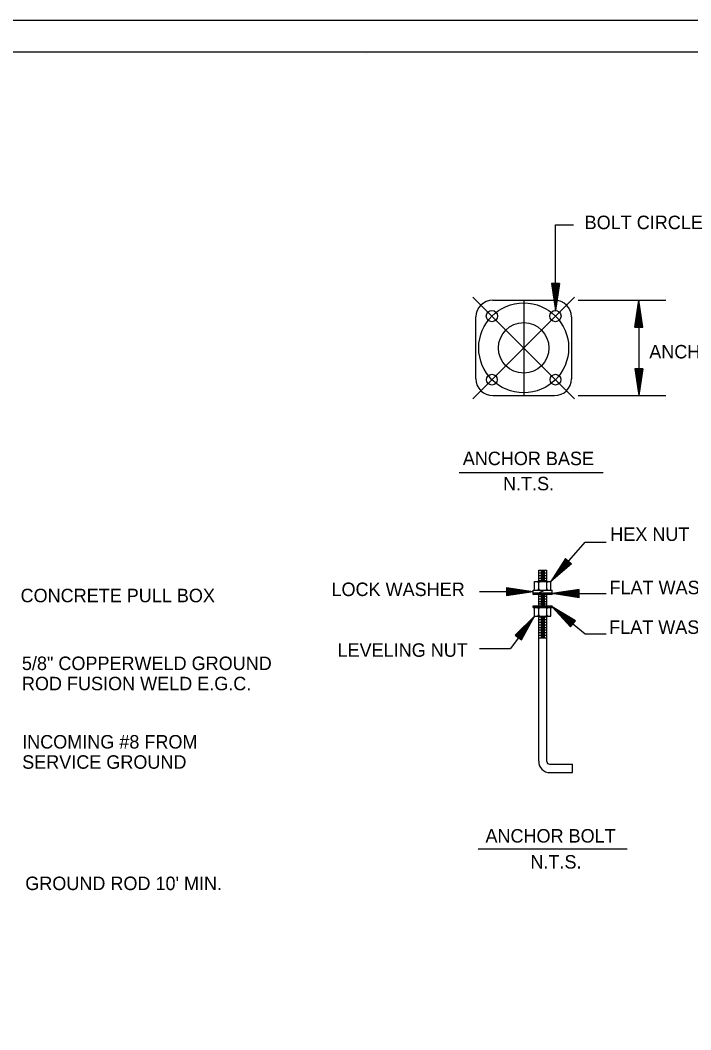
# Model space of a CAD drawing. Extents: x 1370140 to 1371141, y 380020 to 380660.
# Drawn here: x 1370506.7 to 1370755.4, y 380285.7 to 380660 of the extents above; entities that cross this region are included whole.
import ezdxf

# ---------------------------------------------------------------- set-up
doc = ezdxf.new("R2010")
doc.units = 0
for name, color, linetype in [('R_Border', 7, 'Continuous'), ('R_Draft', 7, 'Continuous'), ('R_No Plot', 7, 'Continuous')]:
    doc.layers.add(name, color=color, linetype=linetype)

msp = doc.modelspace()

# ---------------------------------------------------------------- linework, layer by layer
at = {"layer": 'R_Border'}
for p, q in [((1370177.71, 380648.36), (1371126.25, 380648.36)), ((1370635.27, 380647.58), (1370635.27, 380647.58)), ((1370635.27, 380647.58), (1370635.27, 380647.58))]:
    msp.add_line(p, q, dxfattribs=at)
at = {"layer": 'R_Draft'}
for p, q in [((1370705.18, 380552.4), (1370705.18, 380584.17)), ((1370705.18, 380584.17), (1370711.89, 380584.17)), ((1370703.68, 380562.4), (1370705.18, 380552.4)), ((1370706.68, 380562.4), (1370703.68, 380562.4)), ((1370703.93, 380562.4), (1370705.18, 380554.07)), ((1370704.19, 380562.4), (1370705.18, 380555.79)), ((1370704.44, 380562.4), (1370705.18, 380557.46)), ((1370704.69, 380562.4), (1370705.18, 380559.15)), ((1370704.95, 380562.4), (1370705.18, 380560.82)), ((1370706.68, 380562.4), (1370705.18, 380552.4)), ((1370705.67, 380562.4), (1370705.18, 380559.15)), ((1370706.18, 380562.4), (1370705.18, 380555.79)), ((1370706.43, 380562.4), (1370705.18, 380554.07)), ((1370705.93, 380562.4), (1370705.18, 380557.46)), ((1370705.42, 380562.4), (1370705.18, 380560.82)), ((1370712.25, 380519.68), (1370674.54, 380557.39)), ((1370674.54, 380519.68), (1370712.25, 380557.39)), ((1370681.94, 380556.24), (1370704.85, 380556.24)), ((1370693.4, 380556.24), (1370693.4, 380520.83)), ((1370713.6, 380556.24), (1370746.1, 380556.24)), ((1370734.6, 380546.24), (1370736.1, 380556.24)), ((1370734.85, 380546.24), (1370736.1, 380554.57)), ((1370736.1, 380556.24), (1370736.1, 380520.83)), ((1370737.6, 380546.24), (1370736.1, 380556.24)), ((1370737.35, 380546.24), (1370736.1, 380554.57)), ((1370735.11, 380546.24), (1370736.1, 380552.85)), ((1370735.36, 380546.24), (1370736.1, 380551.19)), ((1370737.1, 380546.24), (1370736.1, 380552.85)), ((1370736.85, 380546.24), (1370736.1, 380551.19)), ((1370675.69, 380527.08), (1370675.69, 380549.99)), ((1370711.1, 380549.99), (1370711.1, 380527.08)), ((1370735.62, 380546.24), (1370736.1, 380549.49)), ((1370735.87, 380546.24), (1370736.1, 380547.82)), ((1370736.59, 380546.24), (1370736.1, 380549.49)), ((1370736.34, 380546.24), (1370736.1, 380547.82)), ((1370734.6, 380546.24), (1370737.6, 380546.24)), ((1370734.6, 380530.83), (1370736.1, 380520.83)), ((1370737.6, 380530.83), (1370734.6, 380530.83)), ((1370734.85, 380530.83), (1370736.1, 380522.5)), ((1370735.11, 380530.83), (1370736.1, 380524.22)), ((1370735.36, 380530.83), (1370736.1, 380525.88)), ((1370735.61, 380530.83), (1370736.1, 380527.58)), ((1370735.87, 380530.83), (1370736.1, 380529.25)), ((1370737.6, 380530.83), (1370736.1, 380520.83)), ((1370736.59, 380530.83), (1370736.1, 380527.58)), ((1370737.1, 380530.83), (1370736.1, 380524.22)), ((1370737.35, 380530.83), (1370736.1, 380522.5)), ((1370736.85, 380530.83), (1370736.1, 380525.88)), ((1370736.34, 380530.83), (1370736.1, 380529.25)), ((1370681.94, 380520.83), (1370704.85, 380520.83)), ((1370713.6, 380520.83), (1370746.1, 380520.83)), ((1370722.87, 380492.15), (1370669.44, 380492.15)), ((1370703.46, 380451.91), (1370716.15, 380466.53)), ((1370716.15, 380466.53), (1370723.96, 380466.53)), ((1370708.86, 380460.46), (1370703.46, 380451.91)), ((1370711.13, 380458.51), (1370708.86, 380460.46)), ((1370711.13, 380458.51), (1370703.46, 380451.91)), ((1370709.05, 380460.3), (1370704.55, 380453.18)), ((1370710.94, 380458.67), (1370704.55, 380453.18)), ((1370709.24, 380460.13), (1370705.68, 380454.48)), ((1370710.75, 380458.84), (1370705.68, 380454.48)), ((1370709.43, 380459.97), (1370706.76, 380455.74)), ((1370710.56, 380459), (1370706.76, 380455.74)), ((1370709.62, 380459.8), (1370707.87, 380457.02)), ((1370710.36, 380459.17), (1370707.87, 380457.02)), ((1370709.81, 380459.64), (1370708.96, 380458.29)), ((1370710.17, 380459.33), (1370708.96, 380458.29)), ((1370698.96, 380456.08), (1370701.96, 380456.08)), ((1370698.96, 380451.91), (1370698.96, 380456.08)), ((1370698.96, 380455.12), (1370701.96, 380455.12)), ((1370698.96, 380454.15), (1370701.96, 380454.15)), ((1370698.96, 380453.19), (1370701.96, 380453.19)), ((1370699.71, 380455.58), (1370701.21, 380455.58)), ((1370699.71, 380454.62), (1370701.21, 380454.62)), ((1370699.71, 380453.65), (1370701.21, 380453.65)), ((1370701.96, 380451.91), (1370701.96, 380456.08)), ((1370686.96, 380449.75), (1370696.96, 380448.25)), ((1370686.96, 380449.75), (1370686.96, 380446.75)), ((1370686.96, 380449.5), (1370695.29, 380448.25)), ((1370686.96, 380449.25), (1370693.57, 380448.25)), ((1370697.46, 380448.75), (1370697.46, 380451.91)), ((1370697.46, 380451.91), (1370703.46, 380451.91)), ((1370698.96, 380452.23), (1370701.96, 380452.23)), ((1370698.96, 380448.75), (1370698.96, 380451.91)), ((1370699.71, 380452.69), (1370701.21, 380452.69)), ((1370701.96, 380448.75), (1370701.96, 380451.91)), ((1370703.46, 380448.75), (1370703.46, 380451.91)), ((1370676.97, 380448.25), (1370696.96, 380448.25)), ((1370686.96, 380449), (1370691.91, 380448.25)), ((1370686.96, 380448.74), (1370690.21, 380448.25)), ((1370686.96, 380448.49), (1370688.54, 380448.25)), ((1370686.96, 380446.75), (1370696.96, 380448.25)), ((1370686.96, 380447.76), (1370690.21, 380448.25)), ((1370686.96, 380447.26), (1370693.57, 380448.25)), ((1370686.96, 380447), (1370695.29, 380448.25)), ((1370686.96, 380447.51), (1370691.91, 380448.25)), ((1370686.96, 380448.02), (1370688.54, 380448.25)), ((1370696.96, 380447.08), (1370696.96, 380448.75)), ((1370696.96, 380448.75), (1370703.96, 380448.75)), ((1370696.96, 380447.75), (1370703.96, 380447.75)), ((1370696.96, 380447.12), (1370697.6, 380447.75)), ((1370696.96, 380447.47), (1370697.24, 380447.75)), ((1370703.96, 380447.08), (1370696.96, 380447.08)), ((1370697.28, 380447.08), (1370697.95, 380447.75)), ((1370697.64, 380447.08), (1370698.3, 380447.75)), ((1370697.99, 380447.08), (1370698.66, 380447.75)), ((1370698.34, 380447.08), (1370699.01, 380447.75)), ((1370698.7, 380447.08), (1370699.36, 380447.75)), ((1370698.96, 380442.92), (1370698.96, 380447.08)), ((1370698.96, 380446.46), (1370701.96, 380446.46)), ((1370698.96, 380445.5), (1370701.96, 380445.5)), ((1370698.97, 380447.75), (1370701.16, 380448.72)), ((1370699.05, 380447.08), (1370699.72, 380447.75)), ((1370699.4, 380447.08), (1370700.07, 380447.75)), ((1370699.71, 380446.92), (1370701.21, 380446.92)), ((1370699.71, 380445.96), (1370701.21, 380445.96)), ((1370699.76, 380447.08), (1370700.42, 380447.75)), ((1370700.11, 380447.08), (1370700.78, 380447.75)), ((1370700.46, 380447.08), (1370701.13, 380447.75)), ((1370700.82, 380447.08), (1370701.48, 380447.75)), ((1370701.17, 380447.08), (1370701.84, 380447.75)), ((1370701.52, 380447.08), (1370702.19, 380447.75)), ((1370701.88, 380447.08), (1370702.55, 380447.75)), ((1370701.96, 380442.92), (1370701.96, 380447.08)), ((1370702.23, 380447.08), (1370702.9, 380447.75)), ((1370702.59, 380447.08), (1370703.25, 380447.75)), ((1370702.94, 380447.08), (1370703.61, 380447.75)), ((1370703.29, 380447.08), (1370703.96, 380447.75)), ((1370703.65, 380447.08), (1370703.96, 380447.4)), ((1370713.96, 380448.92), (1370703.96, 380447.42)), ((1370703.96, 380447.08), (1370703.96, 380448.75)), ((1370703.96, 380447.42), (1370723.96, 380447.42)), ((1370713.96, 380445.92), (1370703.96, 380447.42)), ((1370713.96, 380448.67), (1370705.63, 380447.42)), ((1370713.96, 380446.17), (1370705.63, 380447.42)), ((1370713.96, 380448.41), (1370707.35, 380447.42)), ((1370713.96, 380446.42), (1370707.35, 380447.42)), ((1370713.96, 380448.16), (1370709.02, 380447.42)), ((1370713.96, 380446.67), (1370709.02, 380447.42)), ((1370713.96, 380447.91), (1370710.71, 380447.42)), ((1370713.96, 380446.93), (1370710.71, 380447.42)), ((1370713.96, 380447.65), (1370712.38, 380447.42)), ((1370713.96, 380447.18), (1370712.38, 380447.42)), ((1370713.96, 380445.92), (1370713.96, 380448.92)), ((1370696.96, 380442.25), (1370696.96, 380442.92)), ((1370696.96, 380442.92), (1370703.96, 380442.92)), ((1370696.96, 380442.58), (1370697.3, 380442.92)), ((1370696.96, 380442.25), (1370703.96, 380442.25)), ((1370696.99, 380442.25), (1370697.65, 380442.92)), ((1370697.34, 380442.25), (1370698.01, 380442.92)), ((1370697.46, 380439.09), (1370697.46, 380442.25)), ((1370697.69, 380442.25), (1370698.36, 380442.92)), ((1370698.05, 380442.25), (1370698.72, 380442.92)), ((1370698.4, 380442.25), (1370699.07, 380442.92)), ((1370698.76, 380442.25), (1370699.42, 380442.92)), ((1370698.96, 380444.54), (1370701.96, 380444.54)), ((1370698.96, 380443.58), (1370701.96, 380443.58)), ((1370698.96, 380439.09), (1370698.96, 380442.25)), ((1370699.11, 380442.25), (1370699.78, 380442.92)), ((1370699.46, 380442.25), (1370700.13, 380442.92)), ((1370699.71, 380445), (1370701.21, 380445)), ((1370699.71, 380444.04), (1370701.21, 380444.04)), ((1370699.71, 380443.08), (1370701.21, 380443.08)), ((1370699.82, 380442.25), (1370700.48, 380442.92)), ((1370700.17, 380442.25), (1370700.84, 380442.92)), ((1370700.52, 380442.25), (1370701.19, 380442.92)), ((1370700.88, 380442.25), (1370701.54, 380442.92)), ((1370701.23, 380442.25), (1370701.9, 380442.92)), ((1370701.58, 380442.25), (1370702.25, 380442.92)), ((1370701.94, 380442.25), (1370702.6, 380442.92)), ((1370701.96, 380439.09), (1370701.96, 380442.25)), ((1370702.29, 380442.25), (1370702.96, 380442.92)), ((1370702.64, 380442.25), (1370703.31, 380442.92)), ((1370703, 380442.25), (1370703.66, 380442.92)), ((1370703.35, 380442.25), (1370703.96, 380442.86)), ((1370703.46, 380439.09), (1370703.46, 380442.25)), ((1370703.71, 380442.25), (1370703.96, 380442.51)), ((1370703.96, 380442.25), (1370703.96, 380442.92)), ((1370703.96, 380442.58), (1370716.15, 380432.55)), ((1370710.73, 380435.07), (1370703.96, 380442.58)), ((1370712.64, 380437.39), (1370703.96, 380442.58)), ((1370697.46, 380439.09), (1370688.52, 380427.1)), ((1370690.21, 380432.04), (1370697.46, 380439.09)), ((1370692.6, 380430.23), (1370697.46, 380439.09)), ((1370697.46, 380439.09), (1370703.46, 380439.09)), ((1370698.96, 380385.24), (1370698.96, 380439.09)), ((1370698.96, 380438.77), (1370701.96, 380438.77)), ((1370699.71, 380438.27), (1370701.21, 380438.27)), ((1370701.96, 380385.2), (1370701.96, 380439.09)), ((1370710.89, 380435.26), (1370705.25, 380441.52)), ((1370712.48, 380437.2), (1370705.25, 380441.52)), ((1370712.32, 380437), (1370706.58, 380440.43)), ((1370711.05, 380435.46), (1370706.58, 380440.43)), ((1370711.21, 380435.65), (1370707.87, 380439.37)), ((1370712.16, 380436.81), (1370707.87, 380439.37)), ((1370712, 380436.61), (1370709.18, 380438.29)), ((1370711.38, 380435.86), (1370709.18, 380438.29)), ((1370690.41, 380431.89), (1370696.45, 380437.76)), ((1370690.61, 380431.74), (1370695.41, 380436.39)), ((1370690.81, 380431.59), (1370694.4, 380435.07)), ((1370692, 380430.68), (1370694.4, 380435.07)), ((1370692.2, 380430.53), (1370695.41, 380436.39)), ((1370692.4, 380430.38), (1370696.45, 380437.76)), ((1370698.96, 380437.81), (1370701.96, 380437.81)), ((1370698.96, 380436.85), (1370701.96, 380436.85)), ((1370698.96, 380435.89), (1370701.96, 380435.89)), ((1370698.96, 380434.92), (1370701.96, 380434.92)), ((1370699.71, 380437.31), (1370701.21, 380437.31)), ((1370699.71, 380436.35), (1370701.21, 380436.35)), ((1370699.71, 380435.39), (1370701.21, 380435.39)), ((1370699.71, 380434.42), (1370701.21, 380434.42)), ((1370711.84, 380436.41), (1370710.47, 380437.23)), ((1370711.54, 380436.05), (1370710.47, 380437.23)), ((1370710.73, 380435.07), (1370712.64, 380437.39)), ((1370690.21, 380432.04), (1370692.6, 380430.23)), ((1370691.02, 380431.43), (1370693.37, 380433.72)), ((1370691.22, 380431.28), (1370692.36, 380432.39)), ((1370691.59, 380430.99), (1370692.36, 380432.39)), ((1370691.79, 380430.84), (1370693.37, 380433.72)), ((1370698.96, 380433.96), (1370701.96, 380433.96)), ((1370698.96, 380433), (1370701.96, 380433)), ((1370698.96, 380432.04), (1370701.96, 380432.04)), ((1370698.96, 380431.08), (1370701.96, 380431.08)), ((1370699.71, 380433.46), (1370701.21, 380433.46)), ((1370699.71, 380432.5), (1370701.21, 380432.5)), ((1370699.71, 380431.54), (1370701.21, 380431.54)), ((1370716.15, 380432.55), (1370723.96, 380432.55)), ((1370676.97, 380427.1), (1370688.52, 380427.1)), ((1370702.96, 380384.2), (1370711.46, 380384.2)), ((1370711.46, 380381.08), (1370711.46, 380384.2)), ((1370703.13, 380381.08), (1370711.46, 380381.08)), ((1370731.82, 380352.64), (1370676.56, 380352.64))]:
    msp.add_line(p, q, dxfattribs=at)
for centre, radius in [((1370693.4, 380538.53), 16.67), ((1370681.61, 380550.32), 2.08), ((1370705.18, 380550.32), 2.08), ((1370693.4, 380538.53), 9.37), ((1370681.61, 380526.75), 2), ((1370705.18, 380526.75), 2)]:
    msp.add_circle(centre, radius, dxfattribs=at)
for centre, radius, start, end in [((1370681.94, 380549.99), 6.25, 90, 180), ((1370704.85, 380549.99), 6.25, 360, 90), ((1370681.94, 380527.08), 6.25, 180, 270), ((1370704.85, 380527.08), 6.25, 270, 0), ((1370698.46, 380451.41), 0.5, 0, 90), ((1370698.46, 380449.25), 0.5, 270, 0), ((1370699.46, 380451.41), 0.5, 90, 180), ((1370699.46, 380449.25), 0.5, 180, 270), ((1370701.46, 380451.41), 0.5, 0, 90), ((1370701.46, 380449.25), 0.5, 270, 0), ((1370702.46, 380451.41), 0.5, 90, 180), ((1370702.46, 380449.25), 0.5, 180, 270), ((1370698.46, 380441.75), 0.5, 0, 90), ((1370699.46, 380441.75), 0.5, 90, 180), ((1370701.46, 380441.75), 0.5, 0, 90), ((1370702.46, 380441.75), 0.5, 90, 180), ((1370698.46, 380439.59), 0.5, 270, 0), ((1370699.46, 380439.59), 0.5, 180, 270), ((1370701.46, 380439.59), 0.5, 270, 0), ((1370702.46, 380439.59), 0.5, 180, 270), ((1370703.13, 380385.24), 4.17, 180, 270), ((1370702.96, 380385.2), 1, 180, 270)]:
    msp.add_arc(centre, radius, start, end, dxfattribs=at)
at = {"layer": 'R_No Plot'}
msp.add_line((1370140.51, 380660.04), (1371140.51, 380660.04), dxfattribs=at)
msp.add_lwpolyline([(1370140.49, 380660.04), (1371140.51, 380660.04), (1371140.51, 380020.03), (1370140.49, 380020.03)], close=True, dxfattribs=at)

# ---------------------------------------------------------------- texts
at = {"layer": 'R_Draft'}
for s, p in [('BOLT CIRCLE', (1370716, 380582.56)), ('ANCHOR BASE SQUARE', (1370739.96, 380534.62)), ('ANCHOR BASE', (1370670.8, 380495.05)), ('N.T.S.', (1370685.73, 380485.72)), ('HEX NUT', (1370725.51, 380466.96)), ('CONCRETE PULL BOX', (1370506.8, 380444.22)), ('LOCK WASHER', (1370622.11, 380446.52)), ('FLAT WASHER', (1370725.21, 380447.2)), ('FLAT WASHER', (1370725.1, 380432.5)), ('LEVELING NUT', (1370624.36, 380423.99)), ('5/8" COPPERWELD GROUND ', (1370507.3, 380419.08)), ('ROD FUSION WELD E.G.C.', (1370507.3, 380411.58)), ('INCOMING #8 FROM ', (1370507.39, 380389.98)), ('SERVICE GROUND', (1370507.39, 380382.48)), ('ANCHOR BOLT', (1370679.21, 380355.11)), ('N.T.S.', (1370695.89, 380345.47)), ("GROUND ROD 10' MIN.", (1370508.54, 380337.49))]:
    msp.add_text(s, height=5, dxfattribs=at).set_placement(p)

doc.saveas('drawing.dxf')
